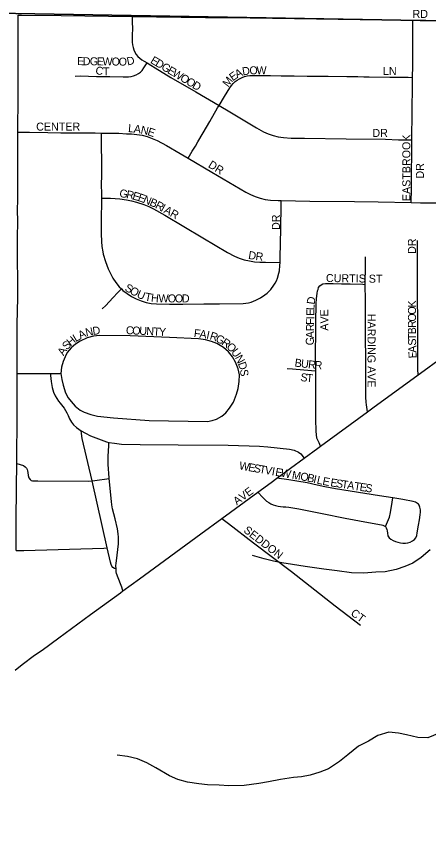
# Model space of a CAD drawing. Extents: x 1874609 to 2204689, y 815661 to 1281160.
# Drawn here: x 2010253 to 2012825, y 1036022 to 1041183 of the extents above; entities that cross this region are included whole.
import ezdxf

# ---------------------------------------------------------------- set-up
doc = ezdxf.new("R2010")
doc.units = 0
for name, color, linetype in [('GM_X_City_Street', 7, 'Continuous'), ('GM_X_City_Street_Text', 7, 'Continuous'), ('GM_X_Minor_River', 7, 'Continuous'), ('GM_X_Section', 7, 'Continuous')]:
    doc.layers.add(name, color=color, linetype=linetype)

msp = doc.modelspace()

# ---------------------------------------------------------------- linework, layer by layer
at = {"layer": 'GM_X_City_Street'}
for points in [[(2010261.5, 1040460.6), (2010261.5, 1040462.1), (2010261.5, 1040520.8), (2010262.4, 1040624.8), (2010262.4, 1040662.1), (2010263.3, 1040738.7), (2010263.7, 1040788.5), (2010264.2, 1040864.1), (2010263.6, 1041001.6), (2010263.3, 1041107.5), (2010262.7, 1041192.4)], [(2010262.7, 1041192.4), (2010285, 1041192.1), (2010530.8, 1041188.7), (2010975.2, 1041183)], [(2010975.2, 1041183), (2010975.9, 1041136), (2010976.1, 1041120), (2010974.8, 1041054.7), (2010975.8, 1041022), (2010977.9, 1041005.8), (2010981.2, 1040989.7), (2010985.6, 1040974.6), (2010992, 1040960.4), (2011000.5, 1040946.3), (2011010.8, 1040933.7), (2011022.8, 1040922.6), (2011035.7, 1040912.7), (2011049.4, 1040903.6), (2011068.1, 1040892.9)], [(2010975.2, 1041183), (2011432.1, 1041177.2), (2011710.6, 1041174), (2011989.1, 1041170.4), (2012398.7, 1041165.5), (2012727.6, 1041161.3)], [(2012725.8, 1040803.1), (2012726.7, 1040876), (2012727.2, 1040925.3), (2012727.7, 1040988.6), (2012728, 1041070), (2012727.7, 1041126), (2012727.6, 1041161.3)], [(2012727.6, 1041161.3), (2012808.4, 1041160.3), (2012899.1, 1041159.1), (2012902.8, 1041159.1)], [(2010620, 1040811.1), (2010652.6, 1040811.5), (2010752.1, 1040808.6), (2010835.2, 1040807.6), (2010918.3, 1040806), (2010951.5, 1040805.8), (2010967.9, 1040807.9), (2010983.8, 1040812.4), (2010999.2, 1040818.9), (2011013.8, 1040826.7), (2011027.2, 1040836.3), (2011037.8, 1040846.2), (2011047.9, 1040861.7), (2011068.1, 1040892.9)], [(2011068.1, 1040892.9), (2011091.9, 1040879.2), (2011119.5, 1040861.8), (2011217.2, 1040802.4), (2011372.4, 1040711.8), (2011517.3, 1040626.8)], [(2011517.3, 1040626.8), (2011551.8, 1040684.2), (2011568.1, 1040711.4), (2011584.3, 1040738.4), (2011594.1, 1040751.9), (2011605.1, 1040764.7), (2011617.5, 1040776.1), (2011631.1, 1040786.1), (2011645.5, 1040794.7), (2011660.6, 1040802), (2011676.4, 1040807.7), (2011692.6, 1040811.9), (2011709.2, 1040814.3), (2011742.1, 1040815.1), (2011806.9, 1040814), (2011839.3, 1040813.9), (2011904.3, 1040813.5), (2011985.6, 1040812), (2012067.2, 1040810.9), (2012197.7, 1040809.8), (2012314.1, 1040808.5), (2012382.7, 1040807.7), (2012420.5, 1040807.3), (2012453.5, 1040806.6), (2012583.1, 1040803.6), (2012697.3, 1040803.2), (2012725.8, 1040803.1)], [(2012721.5, 1040412), (2012721.5, 1040418.7), (2012721.2, 1040467.6), (2012722.7, 1040532.4), (2012723.8, 1040626.1), (2012724.9, 1040721.1), (2012725.6, 1040784.5), (2012725.8, 1040803.1)], [(2011323.8, 1040298.4), (2011349.6, 1040340.8), (2011369.7, 1040373.9), (2011385.5, 1040400.1), (2011418.7, 1040455.8), (2011459.8, 1040527.1), (2011508.6, 1040612.4), (2011517.3, 1040626.8)], [(2011517.3, 1040626.8), (2011583.9, 1040587.8), (2011667.1, 1040536.8), (2011751.2, 1040486.8), (2011794.3, 1040463.5), (2011824.1, 1040450.2), (2011855, 1040439.5), (2011886.7, 1040431.8), (2011919.1, 1040427.2), (2011968, 1040423.5), (2012049.7, 1040422.1), (2012311, 1040418.5), (2012556.1, 1040416), (2012637.6, 1040412.8), (2012686.3, 1040412.4), (2012721.5, 1040412)], [(2010257, 1038953.5), (2010257.1, 1038998.4), (2010257.8, 1039261.2), (2010260.9, 1039425.3), (2010260.3, 1039554.5), (2010259.8, 1039645.4), (2010259, 1039804), (2010260.5, 1039900.4), (2010259.6, 1039976.6), (2010260.5, 1040035.8), (2010260.5, 1040094.1), (2010261.4, 1040137), (2010261.5, 1040220), (2010261.5, 1040460.6)], [(2010261.5, 1040460.6), (2010300.5, 1040460.9), (2010333.4, 1040461.2), (2010448.5, 1040458.4), (2010530.5, 1040456.9), (2010661.7, 1040456.1), (2010743.8, 1040455.6), (2010780.8, 1040455.1)], [(2010780.8, 1040455.1), (2010858.2, 1040454.2), (2010874.4, 1040454), (2010890.7, 1040453.7), (2010938.6, 1040451.1), (2010970.9, 1040449.1), (2011003.7, 1040446.3), (2011036.6, 1040441), (2011068.7, 1040432.4), (2011100, 1040421.2), (2011130.4, 1040407.8), (2011188.7, 1040376.9), (2011274.4, 1040328), (2011323.8, 1040298.4)], [(2010780.8, 1040455.1), (2010781.4, 1040416.5), (2010784.1, 1040235.8), (2010783.8, 1040186.6), (2010782.4, 1040137.3), (2010783, 1040071.6), (2010783.2, 1040048.2)], [(2012716.9, 1040020.7), (2012717.9, 1040105), (2012718.6, 1040161.3), (2012719.5, 1040237.1), (2012720.2, 1040295.1), (2012720.7, 1040346.1), (2012721.5, 1040412)], [(2011323.8, 1040298.4), (2011471.7, 1040209.7), (2011684.7, 1040085.5), (2011713.3, 1040070.3), (2011743.2, 1040057.8), (2011774.2, 1040048), (2011805.8, 1040040.2), (2011837.7, 1040035.2), (2011886.5, 1040032.8), (2011905.7, 1040032.5)], [(2012716.9, 1040020.7), (2012774, 1040019.4), (2012897.5, 1040018), (2012921.9, 1040017.7), (2012970.8, 1040019), (2013003.2, 1040021.9), (2013034.9, 1040027.6), (2013065.7, 1040037.3), (2013095.4, 1040050.1), (2013123.8, 1040065.7), (2013150.8, 1040083.8), (2013230.2, 1040143.5)], [(2010783.2, 1040048.2), (2010783.3, 1040022.4), (2010782, 1039924.1), (2010782.1, 1039871), (2010782.3, 1039825.2), (2010782.5, 1039777.8), (2010786, 1039745.1), (2010790.9, 1039712.9), (2010794.2, 1039697.3), (2010809.3, 1039652.8), (2010826, 1039607), (2010839.6, 1039577.1), (2010855.2, 1039548.2), (2010873.1, 1039520.6), (2010893.7, 1039495), (2010907.8, 1039481)], [(2010783.2, 1040048.2), (2010840.6, 1040048.8), (2010898.7, 1040043.5), (2010939, 1040037.4), (2010971, 1040032.2), (2011002.2, 1040024), (2011048.6, 1040008.3), (2011078.9, 1039996.1), (2011108.3, 1039982), (2011179, 1039941.6), (2011416.2, 1039800.5), (2011570.5, 1039708.6), (2011613.7, 1039685.5), (2011643.7, 1039672.8), (2011674.9, 1039663), (2011706.7, 1039656), (2011739.1, 1039651.2), (2011771.6, 1039648.5), (2011807.7, 1039647.8), (2011897.9, 1039646.4)], [(2011897.9, 1039646.4), (2011898.2, 1039676.4), (2011903.2, 1039856.9), (2011905.3, 1040004.7), (2011905.7, 1040032.5)], [(2011905.7, 1040032.5), (2012083.7, 1040030.2), (2012363.1, 1040027.8), (2012511.1, 1040025.2), (2012716.9, 1040020.7)], [(2012759.3, 1038943.2), (2012759.1, 1038979.5), (2012758.5, 1039075.2), (2012757.9, 1039166.8), (2012757.4, 1039305.8), (2012757, 1039402.6), (2012756.7, 1039474.8), (2012756.4, 1039555.8), (2012756, 1039635), (2012755.7, 1039721.2), (2012755.5, 1039782.8)], [(2012429.8, 1039509.6), (2012430.4, 1039550.6), (2012430.9, 1039584), (2012431.4, 1039612.2), (2012432.3, 1039665.5), (2012431.9, 1039681.7)], [(2010907.8, 1039481), (2010916.9, 1039471.9), (2010942.8, 1039451.6), (2010970.6, 1039434.2), (2011000, 1039419.4), (2011030.4, 1039407), (2011061.8, 1039397.1), (2011094, 1039390.9), (2011126.7, 1039388), (2011208.8, 1039386.3), (2011290.9, 1039386), (2011422.3, 1039386.9), (2011520.8, 1039387.9), (2011668.5, 1039389.6), (2011684.9, 1039391.1), (2011701, 1039394.1), (2011716.9, 1039398.3), (2011732.5, 1039403.6), (2011747.6, 1039409.9), (2011776.6, 1039425.3), (2011803.9, 1039443.6), (2011816.8, 1039453.8), (2011828.9, 1039464.9), (2011839.9, 1039477.1), (2011859.5, 1039503.5), (2011868, 1039517.5), (2011875.6, 1039532.1), (2011882, 1039547.2), (2011891.2, 1039578.8), (2011894.3, 1039594.8), (2011897.7, 1039627.5), (2011897.9, 1039646.4)], [(2012146.1, 1039500.3), (2012155, 1039507.4), (2012165, 1039512.8), (2012181.1, 1039515.7), (2012229.5, 1039514.6), (2012282.3, 1039513.4), (2012335.1, 1039512.2), (2012414.3, 1039510), (2012429.8, 1039509.6)], [(2012444.6, 1038713.1), (2012438.1, 1038757.1), (2012435.8, 1038773.1), (2012433.4, 1038805.6), (2012433.2, 1038821.9), (2012433.1, 1038871.1), (2012433, 1038895.7), (2012433, 1038932.7), (2012432.9, 1038985.5), (2012432.7, 1039071.7), (2012432.5, 1039152.7), (2012432.3, 1039246.2), (2012431.9, 1039290), (2012431.2, 1039362.2), (2012430.7, 1039413.2), (2012429.9, 1039505.1), (2012429.8, 1039509.6)], [(2010787.7, 1039357.2), (2010810.7, 1039378.3), (2010853.2, 1039424.5), (2010885.3, 1039457.7), (2010907.8, 1039481)], [(2012120.5, 1038969.9), (2012120.2, 1039080), (2012120.2, 1039128.3), (2012120.5, 1039160.7), (2012121.2, 1039192.6), (2012121.6, 1039273.5), (2012123.6, 1039387.5), (2012125.6, 1039420.2), (2012129.6, 1039453), (2012132.8, 1039469.3), (2012135.2, 1039477.9), (2012139.1, 1039489.8), (2012146.1, 1039500.3)], [(2010529.8, 1038953.4), (2010535.9, 1038915.8), (2010543.3, 1038878.8), (2010559.6, 1038831.4), (2010574.4, 1038800.4), (2010593.6, 1038776.7), (2010618.3, 1038749.4), (2010651.3, 1038723.4), (2010675, 1038710.1), (2010716.6, 1038695.3), (2010759.3, 1038686.4), (2010858.4, 1038676), (2011081.9, 1038659.8), (2011444.3, 1038653.5), (2011474, 1038658.3), (2011502.1, 1038667.1), (2011534.7, 1038686.4), (2011559.8, 1038707.1), (2011583.5, 1038736.7), (2011607.2, 1038773.7), (2011626.4, 1038822.5), (2011636.8, 1038859.5), (2011642.7, 1038902.4), (2011644.2, 1038943.8), (2011636.8, 1038982.3), (2011619, 1039023.7), (2011601.3, 1039056.3), (2011576.1, 1039087.4), (2011545, 1039115.5), (2011504.1, 1039140), (2011469.6, 1039152.4), (2011432.6, 1039162.8), (2011388.2, 1039168.8), (2011208.3, 1039177.1), (2010962.5, 1039187), (2010770.7, 1039189.4), (2010732.7, 1039185.1), (2010694.5, 1039174.7), (2010649.9, 1039155.5), (2010620.3, 1039134.8), (2010593.6, 1039112.6), (2010569.9, 1039083), (2010556.6, 1039056.4), (2010544.6, 1039027.2), (2010534.4, 1038991.2), (2010529.8, 1038953.4)], [(2012759.3, 1038943.2), (2012796.8, 1038970.6), (2012882.3, 1039034.5)], [(2010254.3, 1038390.6), (2010257, 1038702.5), (2010257, 1038953.5)], [(2010257, 1038953.5), (2010318.4, 1038953.5), (2010464.3, 1038953.5)], [(2010464.3, 1038953.5), (2010465.6, 1038939), (2010469.1, 1038902.3), (2010474.8, 1038864.4), (2010482.9, 1038835.7), (2010494.3, 1038812.8), (2010503.6, 1038795.7), (2010514.5, 1038780.2), (2010525.3, 1038768), (2010550.6, 1038735.8), (2010567.9, 1038706.4), (2010575.1, 1038689.6), (2010583.5, 1038669.7), (2010595.2, 1038648.2), (2010607.9, 1038631.6), (2010626.7, 1038614.6), (2010656, 1038594.4)], [(2010464.3, 1038953.5), (2010529.8, 1038953.4)], [(2011943.1, 1038983.6), (2011976.7, 1038981.7), (2012093.7, 1038972.1), (2012120.5, 1038969.9)], [(2012150.8, 1038498), (2012141.9, 1038518.5), (2012128.7, 1038548.8), (2012123.4, 1038592.3), (2012121.4, 1038666.9), (2012120.9, 1038825.3), (2012120.6, 1038955.6), (2012120.5, 1038969.9)], [(2012444.6, 1038713.1), (2012478.3, 1038737.8), (2012759.3, 1038943.2)], [(2012150.8, 1038498), (2012444.6, 1038713.1)], [(2010726, 1038281.8), (2010662.3, 1038547), (2010658.3, 1038577.3), (2010656, 1038594.4)], [(2010656, 1038594.4), (2010682.6, 1038579.7), (2010714.7, 1038563.6), (2010814.9, 1038524.5), (2010829.2, 1038521.5)], [(2010831.4, 1038296.7), (2010830.9, 1038300.8), (2010826.1, 1038384.5), (2010826, 1038436), (2010828.4, 1038500.4), (2010829.2, 1038521.5)], [(2010829.2, 1038521.5), (2010864.4, 1038516.3), (2010907.3, 1038511.8), (2011025.6, 1038508.8), (2011261.1, 1038507.2), (2011574.6, 1038504.4), (2011769.9, 1038498.4), (2011821.6, 1038494.9), (2011957.8, 1038479.2), (2011985.6, 1038473.2), (2012012.5, 1038460.8), (2012028.8, 1038449.6), (2012049, 1038423.5)], [(2012049, 1038423.5), (2012133.6, 1038485.4), (2012150.8, 1038498)], [(2011878.9, 1038299.1), (2012049, 1038423.5)], [(2010249.8, 1037845.8), (2010250.7, 1037913.5), (2010250.6, 1038028.7), (2010253, 1038242.2), (2010254.3, 1038390.6)], [(2010254.3, 1038390.6), (2010297.3, 1038376.6), (2010307.8, 1038369.8), (2010314.3, 1038361.6), (2010318.4, 1038353.4), (2010321.8, 1038343.4), (2010323, 1038334.6), (2010325.7, 1038315.8), (2010329.8, 1038301.1), (2010337.2, 1038290.5), (2010345.4, 1038284), (2010353.5, 1038282.3), (2010385.4, 1038281.5), (2010702.4, 1038279.9), (2010726, 1038281.8)], [(2010726, 1038281.8), (2010742.4, 1038283.2), (2010771, 1038287.2), (2010802.7, 1038292.2), (2010831.4, 1038296.7)], [(2010819.8, 1037862.6), (2010726, 1038281.8)], [(2010874.2, 1037732.3), (2010873.6, 1037751.3), (2010875.1, 1037768), (2010876.4, 1037781.5), (2010889.1, 1037888.5), (2010890.4, 1037912.6), (2010890.4, 1037929.8), (2010888, 1037951.3), (2010883.5, 1037981.5), (2010869.7, 1038044.6), (2010852.5, 1038106.7), (2010847.9, 1038131.9), (2010845.6, 1038153.7), (2010831.4, 1038296.7)], [(2011758.5, 1038210.9), (2011841.8, 1038271.9), (2011878.9, 1038299.1)], [(2012602.8, 1038174.7), (2012518.6, 1038188.8), (2012243.3, 1038232.7), (2012178.5, 1038243.7), (2012130.3, 1038254), (2012066.7, 1038269), (2012002.3, 1038280.2), (2011953.7, 1038287.7), (2011878.9, 1038299.1)], [(2011534.7, 1038046.9), (2011758.5, 1038210.9)], [(2011758.5, 1038210.9), (2011791.1, 1038176.9), (2011802.1, 1038165.4), (2011814.2, 1038155), (2011827.1, 1038145.6), (2011840.9, 1038137.9), (2011855.5, 1038131.4), (2011870.5, 1038126.7), (2011886, 1038123), (2011901.8, 1038120.7), (2011917.4, 1038119.4), (2011934.4, 1038119.2), (2011951.9, 1038117.4), (2012015.7, 1038106.1), (2012160.6, 1038077.6), (2012305.4, 1038049.5), (2012450.3, 1038021.8), (2012531.6, 1038007.6), (2012540, 1038004.7), (2012548.2, 1038000.9), (2012555.5, 1037995.7)], [(2012555.5, 1037995.7), (2012569.7, 1038026), (2012575.5, 1038039.6), (2012581, 1038054.3), (2012587.6, 1038084.9), (2012598.3, 1038147.8), (2012602.8, 1038174.7)], [(2012555.5, 1037995.7), (2012555.6, 1037995.6), (2012560.7, 1037987.4), (2012564.1, 1037978.7), (2012566, 1037970.2), (2012568, 1037953.8), (2012571.9, 1037939.1), (2012579.2, 1037926.2), (2012590.3, 1037916.3), (2012603.9, 1037908.2), (2012618.2, 1037902), (2012633.5, 1037897.9), (2012649.4, 1037894.9), (2012665.3, 1037893), (2012681.2, 1037892.2), (2012696.6, 1037893.6), (2012710.8, 1037898.5), (2012724.6, 1037906.2), (2012737.2, 1037915.4), (2012746.3, 1037926.4), (2012751.2, 1037941.1), (2012754.6, 1037956.5), (2012763.3, 1038005.1), (2012768.9, 1038037.1), (2012773.5, 1038069.6), (2012775.2, 1038085.1), (2012773.9, 1038100.4), (2012771, 1038116.3), (2012766.3, 1038130.4), (2012762.1, 1038135.6), (2012756.6, 1038140.5), (2012750.3, 1038144.7), (2012743.3, 1038147.5), (2012728.2, 1038151.8), (2012664.2, 1038164.4), (2012602.8, 1038174.7)], [(2010917.5, 1037593.6), (2011020.4, 1037669.4), (2011404.3, 1037951.4), (2011534.7, 1038046.9)], [(2011534.7, 1038046.9), (2011576, 1038015), (2011732.7, 1037893.9), (2011969.4, 1037714.6), (2012086.5, 1037623.4), (2012242.5, 1037501.4), (2012399.4, 1037380.8)], [(2010249.8, 1037845.8), (2010298.7, 1037847.3), (2010797.7, 1037862), (2010819.8, 1037862.6)], [(2010874.2, 1037732.3), (2010864.2, 1037733.9), (2010854, 1037740.4), (2010847.5, 1037749.1), (2010843.4, 1037759.9), (2010839.5, 1037774.5), (2010819.8, 1037862.6)], [(2010917.5, 1037593.6), (2010909.6, 1037617.4), (2010883.2, 1037685.8), (2010881, 1037693.1), (2010877.7, 1037703.8), (2010875.6, 1037714.1), (2010874.3, 1037729.5), (2010874.2, 1037732.3)], [(2010245, 1037099.4), (2010288.5, 1037135), (2010365.8, 1037192.9), (2010412.6, 1037224.3), (2010516.6, 1037300.5), (2010715, 1037446.5), (2010901.1, 1037581.6), (2010917.5, 1037593.6)]]:
    msp.add_lwpolyline(points, dxfattribs=at)
at = {"layer": 'GM_X_Minor_River'}
for points in [[(2012835.7, 1037851.4), (2012779.4, 1037803.4), (2012727.1, 1037767.5), (2012676.9, 1037745.6), (2012622.7, 1037727.7), (2012554.5, 1037713.9), (2012496.3, 1037710.1), (2012420.1, 1037704.4), (2012343.8, 1037706.6), (2012255.6, 1037719), (2012171.4, 1037729.3), (2012055.1, 1037745.8), (2011974.9, 1037758.1), (2011908.8, 1037770.3), (2011856.6, 1037780.6), (2011798.5, 1037794.8), (2011726.4, 1037815.1)], [(2012890.6, 1036705.5), (2012820.3, 1036675.6), (2012758.1, 1036677.8), (2012688, 1036694.1), (2012637.8, 1036704.3), (2012577.7, 1036710.6), (2012509.4, 1036690.8), (2012451.2, 1036654.8), (2012386.9, 1036623), (2012320.5, 1036569), (2012268.3, 1036527.1), (2012200, 1036483.2), (2012145.7, 1036461.3), (2012085.5, 1036443.4), (2012031.3, 1036431.6), (2011981.2, 1036427.7), (2011900.9, 1036416), (2011826.6, 1036400.2), (2011766.4, 1036390.4), (2011674.1, 1036378.6), (2011577.9, 1036377), (2011517.7, 1036379.2), (2011445.5, 1036381.4), (2011391.4, 1036387.7), (2011321.2, 1036399.9), (2011259.1, 1036416.2), (2011207, 1036438.4), (2011122.9, 1036488.9), (2011066.8, 1036519.2), (2011008.7, 1036545.5), (2010946.6, 1036559.7), (2010880.4, 1036568)]]:
    msp.add_lwpolyline(points, dxfattribs=at)
at = {"layer": 'GM_X_Section'}
for points in [[(2012915.3, 1046513.3), (2012892.7, 1041156.5), (2007599.8, 1041247.3), (2007626.4, 1046598.1)], [(2007599.8, 1041247.3), (2012892.7, 1041156.5), (2012877.9, 1035897.7), (2011531.4, 1035800.8), (2010681, 1035777), (2010086.6, 1035805.8), (2009320.1, 1035878.2), (2007577.2, 1035888.5)]]:
    msp.add_lwpolyline(points, close=True, dxfattribs=at)

# ---------------------------------------------------------------- texts
at = {"layer": 'GM_X_City_Street_Text'}
for s, rotation, p in [('RD', 0, (2012725.2, 1041174.3)), ('E', 359.3443, (2010630.9, 1040879.5)), ('D', 359.3566, (2010666.1, 1040879.1)), ('G', 359.3443, (2010710.1, 1040878.6)), ('E', 359.3543, (2010754.1, 1040878.1)), ('W', 359.3443, (2010789.3, 1040877.7)), ('O', 359.3566, (2010846.5, 1040877.1)), ('O', 359.3443, (2010890.5, 1040876.6)), ('D', 11.8893, (2010946.4, 1040877.3)), ('E', 329.1909, (2011084.4, 1040895.8)), ('D', 329.1996, (2011114.6, 1040877.8)), ('C', 347.4896, (2010741.9, 1040825.5)), ('T', 359.8506, (2010792.2, 1040815.6)), ('G', 329.2087, (2011152.4, 1040855.2)), ('E', 329.1909, (2011190.2, 1040832.7)), ('W', 329.1921, (2011220.4, 1040814.7)), ('A', 25.2256, (2011629.5, 1040797.1)), ('D', 9.4623, (2011665.8, 1040814.7)), ('O', 0.7214, (2011707.2, 1040821.8)), ('W', 0, (2011751.1, 1040822.3)), ('LN', 0, (2012540.4, 1040817.9)), ('O', 329.2087, (2011269.6, 1040785.4)), ('O', 329.1996, (2011307.4, 1040762.9)), ('M', 51.9461, (2011573.2, 1040738.7)), ('E', 35.7663, (2011603, 1040777.7)), ('D', 329.8447, (2011345.7, 1040740)), ('CENTER', 0, (2010375.6, 1040470.3)), ('L', 354.8847, (2010948.1, 1040461.5)), ('A', 352.4805, (2010982.6, 1040458.4)), ('N', 347.6229, (2011025.1, 1040452.9)), ('E', 340.416, (2011066.5, 1040443.9)), ('DR', 0, (2012474.4, 1040430.7)), ('EASTBROOK', 90, (2012711.4, 1040029.7)), ('DR', 327.9873, (2011445.3, 1040244.5)), ('DR', 90, (2012796.4, 1040170.5)), ('G', 349.8046, (2010892.1, 1040056.6)), ('R', 349.5713, (2010935.3, 1040048.8)), ('E', 344.171, (2010973.1, 1040041.9)), ('E', 340.8221, (2011006.2, 1040032.5)), ('N', 337.9551, (2011038.8, 1040021.2)), ('B', 335.749, (2011079.1, 1040004.9)), ('R', 331.719, (2011114.4, 1039989)), ('I', 330.9709, (2011149.1, 1039970.4)), ('A', 330.7947, (2011168.3, 1039959.7)), ('R', 330.826, (2011206.8, 1039938.2)), ('DR', 90, (2011897.4, 1039849.3)), ('DR', 90, (2012746.6, 1039699.7)), ('D', 350.6491, (2011697.3, 1039669.3)), ('R', 353.0885, (2011743, 1039661.9)), ('CURTIS ST', 359.1689, (2012184.2, 1039524.3)), ('S', 332.9095, (2010924.6, 1039472.3)), ('O', 328.3352, (2010955, 1039456.8)), ('U', 336.9918, (2010999.8, 1039430)), ('T', 348.7887, (2011051, 1039409.5)), ('H', 354.2253, (2011090.7, 1039401.9)), ('W', 359.5902, (2011139.5, 1039397.1)), ('O', 359.9929, (2011197.1, 1039396.7)), ('O', 359.9929, (2011241.1, 1039396.7)), ('D', 359.9929, (2011285.1, 1039396.7)), ('D', 82.0399, (2012113.6, 1039381.5)), ('K', 90, (2012746.6, 1039364.4)), ('E', 89.003, (2012111.8, 1039312.7)), ('L', 87.8961, (2012112.5, 1039347.6)), ('O', 90, (2012746.6, 1039320.4)), ('I', 88.9512, (2012111.4, 1039290.6)), ('AVE', 90, (2012199, 1039220.1)), ('HARDING AVE', 270, (2012444.2, 1039325.7)), ('O', 90, (2012746.6, 1039276.4)), ('C', 357.2789, (2010934.8, 1039198.7)), ('R', 88.98, (2012110.1, 1039215.9)), ('F', 88.9892, (2012110.8, 1039255.5)), ('R', 90, (2012746.6, 1039236.8)), ('A', 26.1154, (2010652, 1039165.6)), ('N', 12.2894, (2010688.5, 1039183.9)), ('D', 6.9895, (2010730.3, 1039193.1)), ('O', 357.2664, (2010974.4, 1039196.9)), ('U', 357.2907, (2011018.3, 1039194.8)), ('N', 357.2664, (2011062.3, 1039192.7)), ('T', 357.2672, (2011106.2, 1039190.6)), ('Y', 357.2907, (2011141.4, 1039188.9)), ('F', 352.9902, (2011357.8, 1039181.1)), ('A', 352.4169, (2011392.6, 1039176.8)), ('I', 348.3387, (2011435.3, 1039171.2)), ('R', 342.1332, (2011455.5, 1039167.1)), ('A', 89.0019, (2012109.3, 1039171.9)), ('T', 90.6011, (2012747, 1039162.2)), ('B', 90.0486, (2012746.6, 1039197.2)), ('S', 47.2798, (2010568.1, 1039096.2)), ('H', 39.9637, (2010590.8, 1039120.9)), ('L', 31.1207, (2010622.9, 1039147.9)), ('G', 331.988, (2011491, 1039155.8)), ('R', 325.5152, (2011528.6, 1039135.9)), ('G', 88.9727, (2012108.5, 1039127.9)), ('S', 91.8036, (2012748.1, 1039127.3)), ('A', 58.9051, (2010547, 1039060.6)), ('O', 316.9781, (2011559.7, 1039114.8)), ('U', 305.6241, (2011590.1, 1039086.7)), ('A', 92.0985, (2012749.7, 1039083.3)), ('N', 297.2006, (2011614.8, 1039052.6)), ('B', 352.9141, (2011987.1, 1038996.3)), ('E', 92.1039, (2012751, 1039048.2)), ('D', 289.1261, (2011634.1, 1039015.2)), ('U', 352.8994, (2012026.4, 1038991.4)), ('R', 354.2744, (2012071.4, 1038985.8)), ('R', 355.8556, (2012112.2, 1038981.7)), ('S', 276.132, (2011647.9, 1038976.5)), ('S', 351.3328, (2012022.7, 1038906.8)), ('T', 354.3007, (2012060.3, 1038901.2)), ('W', 350.0485, (2011640, 1038353.8)), ('E', 350.0347, (2011696.3, 1038343.9)), ('S', 350.0423, (2011731, 1038337.8)), ('T', 350.0347, (2011765.7, 1038331.7)), ('V', 350.0347, (2011800.4, 1038325.6)), ('I', 350.0275, (2011843.7, 1038318)), ('E', 350.0423, (2011865.4, 1038314.2)), ('W', 350.0403, (2011900.1, 1038308.2)), ('M', 350.0391, (2011969.4, 1038296)), ('O', 349.6932, (2012021.3, 1038286.9)), ('B', 347.7136, (2012064.2, 1038279.1)), ('I', 347.1299, (2012102.7, 1038270.7)), ('L', 347.126, (2012124.2, 1038265.8)), ('E', 348.7733, (2012160, 1038257.6)), ('E', 351.2566, (2012209.9, 1038248.3)), ('S', 351.3204, (2012244.7, 1038242.9)), ('T', 351.3058, (2012279.5, 1038237.6)), ('A', 351.3103, (2012314.3, 1038232.3)), ('T', 351.3058, (2012357.8, 1038225.6)), ('E', 351.3354, (2012392.6, 1038220.3)), ('AVE', 36.4695, (2011628.4, 1038127.7)), ('S', 351.3328, (2012427.4, 1038215)), ('SEDDON', 322.307, (2011666.1, 1037964.8)), ('CT', 323.7506, (2012334.7, 1037445.7))]:
    msp.add_text(s, height=50, rotation=rotation, dxfattribs=at).set_placement(p)

doc.saveas('drawing.dxf')
